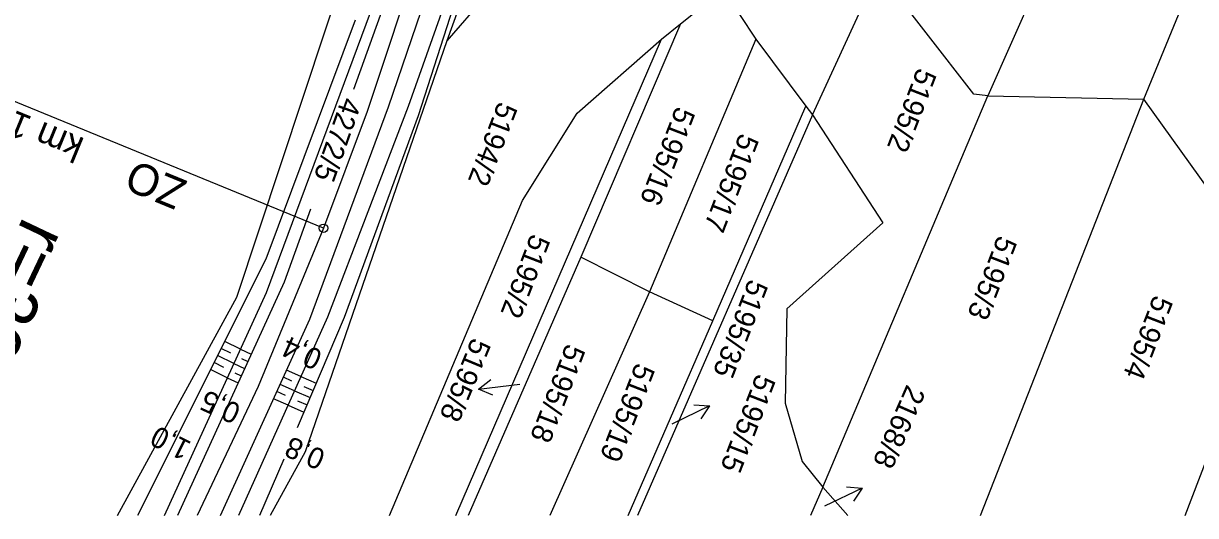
# Model space of a CAD drawing. Extents: x -659211 to -658900, y -1170600 to -1169973.
# Drawn here: x -659140.2 to -659028.5, y -1170600 to -1170553.1 of the extents above; entities that cross this region are included whole.
import ezdxf

# ---------------------------------------------------------------- set-up
doc = ezdxf.new("R2010")
doc.units = 0
for name, color, linetype in [('Vrstva 1', 7, 'Continuous'), ('Vrstva 48', 7, 'Continuous'), ('Vrstva 49', 7, 'Continuous'), ('Vrstva 53', 7, 'Continuous'), ('Vrstva 54', 7, 'Continuous'), ('Vrstva 55', 7, 'Continuous'), ('Vrstva 57', 7, 'Continuous')]:
    doc.layers.add(name, color=color, linetype=linetype)

msp = doc.modelspace()

# ---------------------------------------------------------------- linework, layer by layer
at = {"layer": 'Vrstva 1'}
msp.add_line((-659111.58, -1170572.64), (-659150.87, -1170556.52), dxfattribs=at)
for points in [[(-659102.29, -1170546.02), (-659107.42, -1170561.51), (-659111.58, -1170572.64)], [(-659111.58, -1170572.64), (-659117.79, -1170587.71), (-659123.62, -1170600)]]:
    msp.add_lwpolyline(points, dxfattribs=at)
msp.add_circle((-659111.58, -1170572.64), 0.4, dxfattribs=at)
at = {"layer": 'Vrstva 48'}
for p, q in [((-659120.41, -1170584.55), (-659121.32, -1170584.09)), ((-659119.5, -1170584.17), (-659120.99, -1170583.42)), ((-659119.5, -1170584.17), (-659118.47, -1170584.64)), ((-659120.12, -1170585.53), (-659121.66, -1170584.76)), ((-659119.4, -1170585.04), (-659118.78, -1170585.32)), ((-659120.74, -1170586.9), (-659122.33, -1170586.1)), ((-659121.06, -1170585.9), (-659121.99, -1170585.43)), ((-659120.12, -1170585.53), (-659119.09, -1170586)), ((-659120.02, -1170586.4), (-659119.41, -1170586.68)), ((-659113.74, -1170586.76), (-659115.09, -1170586.14)), ((-659120.74, -1170586.9), (-659119.72, -1170587.36)), ((-659114.35, -1170588.13), (-659115.71, -1170587.51)), ((-659114.59, -1170587.2), (-659115.4, -1170586.82)), ((-659113.74, -1170586.76), (-659112.27, -1170587.39)), ((-659115.2, -1170588.56), (-659116.03, -1170588.19)), ((-659114.35, -1170588.13), (-659112.86, -1170588.77)), ((-659113.45, -1170587.7), (-659112.57, -1170588.08)), ((-659114.96, -1170589.5), (-659116.34, -1170588.87)), ((-659114.96, -1170589.5), (-659113.45, -1170590.14)), ((-659114.06, -1170589.07), (-659113.15, -1170589.46))]:
    msp.add_line(p, q, dxfattribs=at)
at = {"layer": 'Vrstva 49'}
for p, q in [((-659105.38, -1170561.08), (-659096.32, -1170534.47)), ((-659094.24, -1170534.99), (-659103.53, -1170561.06)), ((-659096.72, -1170543.71), (-659102.58, -1170561.93)), ((-659105.91, -1170551.59), (-659108.73, -1170559.44)), ((-659108.57, -1170552.84), (-659117.07, -1170575.58)), ((-659117.02, -1170578.75), (-659107.11, -1170552.1)), ((-659112.89, -1170581.3), (-659105.38, -1170561.08)), ((-659103.53, -1170561.06), (-659111.2, -1170581.1)), ((-659102.58, -1170561.93), (-659109.6, -1170581.13)), ((-659112.83, -1170570.83), (-659115.34, -1170577.79)), ((-659117.07, -1170575.58), (-659129.28, -1170600)), ((-659115.34, -1170577.79), (-659125.49, -1170600)), ((-659126.73, -1170600), (-659117.02, -1170578.75)), ((-659121.4, -1170600), (-659112.89, -1170581.3)), ((-659111.2, -1170581.1), (-659119.67, -1170600)), ((-659109.6, -1170581.13), (-659114.09, -1170591.64)), ((-659115.36, -1170594.62), (-659117.66, -1170600))]:
    msp.add_line(p, q, dxfattribs=at)
at = {"layer": 'Vrstva 53'}
for points in [[(-659119.83, -1170579.19), (-659102.94, -1170528.25), (-659089.69, -1170526.68), (-659099.83, -1170554.8), (-659113.32, -1170593.94), (-659116.65, -1170600)], [(-659131.2, -1170600), (-659119.83, -1170579.19)]]:
    msp.add_lwpolyline(points, dxfattribs=at)
at = {"layer": 'Vrstva 54'}
for p, q in [((-659096.83, -1170587.95), (-659092.87, -1170587.48)), ((-659074.82, -1170589.56), (-659078.41, -1170591.3)), ((-659060.29, -1170597.39), (-659063.88, -1170599.12))]:
    msp.add_line(p, q, dxfattribs=at)
for points in [[(-659095.46, -1170588.55), (-659096.83, -1170587.95), (-659095.65, -1170587.05)], [(-659076.31, -1170589.45), (-659074.82, -1170589.56), (-659075.64, -1170590.8)], [(-659061.78, -1170597.27), (-659060.29, -1170597.39), (-659061.11, -1170598.62)]]:
    msp.add_lwpolyline(points, dxfattribs=at)
at = {"layer": 'Vrstva 55'}
for p, q in [((-659079.72, -1170531.44), (-659099.83, -1170554.8)), ((-659098.97, -1170600), (-659079.39, -1170554.64)), ((-659029.51, -1170600), (-659021.02, -1170577.69))]:
    msp.add_line(p, q, dxfattribs=at)
for points in [[(-659017.26, -1170582.11), (-659019.06, -1170579.82), (-659021.02, -1170577.69), (-659033.45, -1170560.36), (-659016.61, -1170519.32)], [(-659102.94, -1170528.25), (-659089.69, -1170526.68), (-659099.83, -1170554.8)], [(-659119.83, -1170579.19), (-659102.94, -1170528.25), (-659108.2, -1170529.27), (-659126.83, -1170531.09), (-659129.45, -1170531.26)], [(-659039.3, -1170539.7), (-659048.33, -1170560.04), (-659033.45, -1170560.36)], [(-659048.33, -1170560.04), (-659049.64, -1170559.87), (-659058.72, -1170548.15), (-659059.28, -1170547.28)], [(-659105.3, -1170600), (-659092.64, -1170570.01), (-659087.41, -1170561.67), (-659079.39, -1170554.64), (-659077.59, -1170553.17), (-659073.51, -1170549.9), (-659070.4, -1170554.64), (-659065.66, -1170561.02), (-659065.01, -1170561.83), (-659058.72, -1170548.15)], [(-659077.59, -1170553.17), (-659087.08, -1170575.41), (-659097.8, -1170600)], [(-659099.83, -1170554.8), (-659113.32, -1170593.94), (-659116.65, -1170600)], [(-659070.4, -1170554.64), (-659080.54, -1170578.68), (-659090.04, -1170600)], [(-659065.01, -1170561.83), (-659058.3, -1170572.14), (-659067.46, -1170580.31), (-659067.62, -1170589.3), (-659065.99, -1170594.86), (-659064.03, -1170597.31), (-659048.33, -1170560.04)], [(-659049.02, -1170600), (-659033.45, -1170560.36)], [(-659082.57, -1170600), (-659074.49, -1170581.45), (-659065.66, -1170561.02)], [(-659065.01, -1170561.83), (-659081.69, -1170600)], [(-659074.49, -1170581.45), (-659080.54, -1170578.68), (-659087.08, -1170575.41)], [(-659131.2, -1170600), (-659119.83, -1170579.19)], [(-659061.65, -1170600), (-659064.03, -1170597.31), (-659065.2, -1170600)]]:
    msp.add_lwpolyline(points, dxfattribs=at)

# ---------------------------------------------------------------- texts
at = {"layer": 'Vrstva 1'}
for s, height, rotation, p in [('km 1,929', 2.5, 157.6933, (-659134.23, -1170564.13)), ('ZO', 3, 157.6933, (-659124.43, -1170568.19)), ('r=300m', 5, 244.6176, (-659140.12, -1170571.4))]:
    msp.add_text(s, height=height, rotation=rotation, dxfattribs=at).set_placement(p)
at = {"layer": 'Vrstva 48'}
for s, rotation, p in [('0,4', 155.4828, (-659111.55, -1170584.4)), ('0,5', 155.4341, (-659119.31, -1170589.54)), ('1,0', 153.4205, (-659124.05, -1170593.05)), ('0,8', 156.8881, (-659111.26, -1170593.88))]:
    msp.add_text(s, height=2, rotation=rotation, dxfattribs=at).set_placement(p)
at = {"layer": 'Vrstva 57'}
for s, rotation, p in [('5195/2', 248.8639, (-659055, -1170557.27)), ('4272/5', 250.4639, (-659109.8, -1170560.05)), ('5194/2', 248.8639, (-659094.91, -1170560.48)), ('5195/16', 248.8639, (-659077.99, -1170560.94)), ('5195/17', 248.8639, (-659071.92, -1170563.49)), ('5195/2', 248.8639, (-659091.8, -1170573.07)), ('5195/3', 248.8639, (-659047.34, -1170573.23)), ('5195/35', 248.8639, (-659071.05, -1170577.38)), ('5195/4', 248.8639, (-659032.49, -1170578.9)), ('5195/8', 247.3951, (-659097.42, -1170582.96)), ('5195/18', 248.8639, (-659088.45, -1170583.53)), ('5195/19', 248.8639, (-659081.82, -1170585.36)), ('5195/15', 248.8639, (-659070.33, -1170586.4)), ('2168/8', 246.3191, (-659056.02, -1170587.44))]:
    msp.add_text(s, height=2, rotation=rotation, dxfattribs=at).set_placement(p)

doc.saveas('drawing.dxf')
